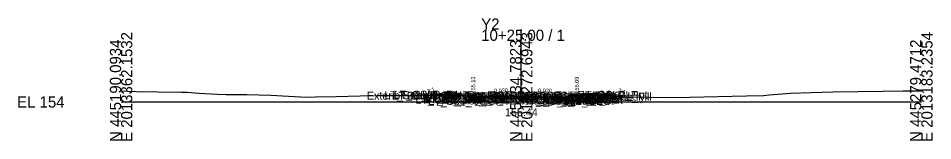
# Model space of a CAD drawing. Extents: x -26 to 203, y -10 to 6017.
# Drawn here: x -25.7 to 202.8, y 490.3 to 520.9 of the extents above; entities that cross this region are included whole.
import ezdxf

# ---------------------------------------------------------------- set-up
doc = ezdxf.new("R2010")
doc.units = 0
for name, color, linetype in [('Default', 7, 'Continuous'), ('Exist CMT Pavement', 7, 'Continuous'), ('Exist Cross Section Cell', 7, 'Continuous'), ('Exist XS Center Line Elevation Label', 7, 'Continuous'), ('Exist XS Ground Line', 7, 'Continuous'), ('Prop CMT Conc Surface', 7, 'Continuous'), ('Prop CMT Concrete Structures', 7, 'Continuous'), ('Prop CMT Pvmt Course 1', 7, 'Continuous'), ('Prop CMT Pvmt Course 1 CG', 7, 'Continuous'), ('Prop CMT Pvmt Course 2', 7, 'Continuous'), ('Prop CMT Pvmt Course 3', 7, 'Continuous'), ('Prop CMT Pvmt Surface', 7, 'Continuous'), ('Prop CMT Pvmt Wedge Surface 1', 7, 'Continuous'), ('Prop CMT Pvmt Wedge Surface 2', 7, 'Continuous'), ('Prop CMT Pvmt Wedge Surface 3', 7, 'Continuous'), ('Prop CMT Slope Grass', 7, 'Continuous'), ('Prop CMT Subgrade Earthwork', 7, 'Continuous'), ('Prop XS Earthwork Shape', 7, 'Continuous'), ('Prop XS Hydro Elevations', 7, 'Continuous'), ('Prop XS SE Text', 7, 'Continuous'), ('Prop XS Side Slope Text', 7, 'Continuous'), ('Scratch_Level_0', 7, 'Continuous')]:
    doc.layers.add(name, color=color, linetype=linetype)

msp = doc.modelspace()

# ---------------------------------------------------------------- linework, layer by layer
at = {"layer": 'Exist CMT Pavement'}
for points in [[(100, 501.44), (99.72, 501.45), (91, 501.36)], [(100, 501.44), (103.09, 501.4), (110.9, 501.16)]]:
    msp.add_lwpolyline(points, dxfattribs=at)
at = {"layer": 'Exist Cross Section Cell'}
for p, q in [((100, 500), (100, 518.08)), ((0, 500), (100, 500)), ((100, 500), (200, 500))]:
    msp.add_line(p, q, dxfattribs=at)
at = {"layer": 'Exist XS Ground Line'}
msp.add_lwpolyline([(0, 502.77), (1.61, 502.73), (3.89, 502.65), (9.07, 502.57), (15.07, 502.46), (16.52, 502.42), (19.43, 502.23), (23.98, 501.98), (26.25, 501.84), (31.43, 501.86), (37.43, 501.69), (41.81, 501.44), (46.34, 501.24), (48.61, 501.28), (53.8, 501.38), (59.79, 501.57), (64.19, 501.63), (70.97, 501.58), (87.75, 501.58), (88.94, 501.44), (89.69, 501.35), (99.72, 501.45), (103.09, 501.4), (111.07, 501.16), (111.56, 501.23), (111.9, 501.66), (124.42, 501.32), (131.99, 501.2), (134.27, 501.15), (142.08, 501.24), (156.34, 501.51), (160.57, 501.64), (162, 501.76), (167.34, 502.2), (172.49, 502.38), (177.94, 502.52), (190.28, 502.7), (195.38, 502.76), (200, 502.79)], dxfattribs=at)
at = {"layer": 'Prop CMT Conc Surface'}
for points in [[(88, 501.13), (88, 501.63), (87.5, 501.63)], [(90, 501.25), (88, 501.13)], [(111.9, 501.21), (113.9, 501.09)], [(113.9, 501.09), (113.9, 501.59), (114.4, 501.59)]]:
    msp.add_lwpolyline(points, dxfattribs=at)
at = {"layer": 'Prop CMT Concrete Structures'}
for points in [[(90, 501.25), (88, 501.13), (88, 501.63), (87.5, 501.63)], [(87.5, 501.63), (87.5, 500.62), (90, 500.67)], [(90, 500.67), (90, 501.25)], [(111.9, 501.21), (113.9, 501.09), (113.9, 501.59), (114.4, 501.59)], [(114.4, 501.59), (114.4, 500.58), (111.9, 500.63)], [(111.9, 500.63), (111.9, 501.21)]]:
    msp.add_lwpolyline(points, dxfattribs=at)
at = {"layer": 'Prop CMT Pvmt Course 1'}
for points in [[(100, 501.45), (90, 501.25)], [(90, 501.25), (90, 501)], [(90, 501), (91, 501.02)], [(91, 501.15), (100, 501.33)], [(91, 501.02), (91, 501.15)], [(100, 501.2), (100, 501.45)], [(100, 501.45), (111.9, 501.21)], [(100, 501.2), (100, 501.45)], [(100, 501.33), (100, 501.2), (100, 501.2)], [(110.9, 501.11), (100, 501.33)], [(100, 501.33), (100, 501.2), (100, 501.2)], [(110.9, 500.98), (110.9, 501.11)], [(111.9, 500.96), (110.9, 500.98)], [(111.9, 501.21), (111.9, 500.96)]]:
    msp.add_lwpolyline(points, dxfattribs=at)
at = {"layer": 'Prop CMT Pvmt Course 1 CG'}
for points in [[(90, 500.67), (87, 500.61), (86.66, 500.27)], [(90, 500.33), (90, 500.67)], [(111.9, 500.63), (114.9, 500.57), (115.24, 500.23)], [(111.9, 500.3), (111.9, 500.63)], [(86.66, 500.27), (90, 500.33)], [(115.24, 500.23), (111.9, 500.3)]]:
    msp.add_lwpolyline(points, dxfattribs=at)
at = {"layer": 'Prop CMT Pvmt Course 2'}
for points in [[(91, 501.02), (90, 501)], [(90, 501), (90, 500.67)], [(90, 500.67), (91, 500.69)], [(91, 500.69), (91, 501.02)], [(110.9, 500.65), (110.9, 500.98)], [(110.9, 500.98), (111.9, 500.96)], [(111.9, 500.63), (110.9, 500.65)], [(111.9, 500.96), (111.9, 500.63)]]:
    msp.add_lwpolyline(points, dxfattribs=at)
at = {"layer": 'Prop CMT Pvmt Course 3'}
for points in [[(91, 500.69), (90, 500.67)], [(90, 500.67), (90, 500.33)], [(91, 500.35), (91, 500.69)], [(110.9, 500.65), (111.9, 500.63)], [(110.9, 500.32), (110.9, 500.65)], [(111.9, 500.63), (111.9, 500.3)], [(90, 500.33), (91, 500.35)], [(111.9, 500.3), (110.9, 500.32)]]:
    msp.add_lwpolyline(points, dxfattribs=at)
at = {"layer": 'Prop CMT Pvmt Surface'}
for points in [[(100, 501.45), (90, 501.25)], [(100, 501.45), (111.9, 501.21)]]:
    msp.add_lwpolyline(points, dxfattribs=at)
at = {"layer": 'Prop CMT Pvmt Wedge Surface 1'}
for points in [[(90, 501), (90, 501.25)], [(91, 501.02), (90, 501)], [(100, 501.33), (91, 501.15)], [(91, 501.15), (91, 501.02)], [(100, 501.33), (110.9, 501.11)], [(110.9, 501.11), (110.9, 500.98)], [(110.9, 500.98), (111.9, 500.96)], [(111.9, 500.96), (111.9, 501.21)]]:
    msp.add_lwpolyline(points, dxfattribs=at)
at = {"layer": 'Prop CMT Pvmt Wedge Surface 2'}
for points in [[(90, 501), (90, 501.25)], [(100, 501.2), (90, 501)], [(100, 501.2), (111.9, 500.96)], [(111.9, 500.96), (111.9, 501.21)]]:
    msp.add_lwpolyline(points, dxfattribs=at)
at = {"layer": 'Prop CMT Pvmt Wedge Surface 3'}
for points in [[(90, 500.67), (90, 501.25)], [(100, 500.87), (90, 500.67)], [(100, 500.87), (111.9, 500.63)], [(111.9, 500.63), (111.9, 501.21)]]:
    msp.add_lwpolyline(points, dxfattribs=at)
at = {"layer": 'Prop CMT Slope Grass'}
for points in [[(87.5, 501.63), (78, 501.82), (77.29, 501.58)], [(114.4, 501.59), (123.9, 501.78), (125.34, 501.3)]]:
    msp.add_lwpolyline(points, dxfattribs=at)
at = {"layer": 'Prop CMT Subgrade Earthwork'}
for points in [[(90, 500.33), (86.66, 500.27), (85.25, 501.68)], [(91, 500.35), (91.01, 501.36)], [(110.9, 500.32), (110.88, 501.16)], [(111.9, 500.3), (115.24, 500.23), (116.65, 501.64)], [(91, 500.35), (90, 500.33)], [(110.9, 500.32), (111.9, 500.3)]]:
    msp.add_lwpolyline(points, dxfattribs=at)
at = {"layer": 'Prop XS Earthwork Shape'}
for points in [[(85.25, 501.68), (78, 501.82), (77.29, 501.58), (85.34, 501.58)], [(85.25, 501.68), (78, 501.82), (77.29, 501.58), (85.34, 501.58)], [(77.29, 501.58), (85.34, 501.58), (85.25, 501.68), (78, 501.82)], [(85.25, 501.68), (78, 501.82), (77.29, 501.58), (85.34, 501.58)], [(85.34, 501.58), (87.5, 501.58), (87.5, 500.62), (90, 500.67), (90, 501.25), (91.01, 501.27), (91, 500.35), (90, 500.33), (86.66, 500.27)], [(85.34, 501.58), (87.5, 501.58), (87.5, 500.62), (90, 500.67), (90, 501.25), (91.01, 501.27), (91, 500.35), (90, 500.33), (86.66, 500.27)], [(85.34, 501.58), (87.5, 501.58), (87.5, 500.62), (90, 500.67), (90, 501.25), (91.01, 501.27), (91, 500.35), (90, 500.33), (86.66, 500.27)], [(85.34, 501.58), (87.5, 501.58), (87.5, 500.62), (90, 500.67), (90, 501.25), (91.01, 501.27), (91, 500.35), (90, 500.33), (86.66, 500.27)], [(87.75, 501.58), (88, 501.56), (88, 501.13), (90, 501.25), (90, 500.67), (87.5, 500.62), (87.5, 501.58)], [(87.75, 501.58), (88, 501.56), (88, 501.13), (90, 501.25), (90, 500.67), (87.5, 500.62), (87.5, 501.58)], [(87.75, 501.58), (88, 501.56), (88, 501.13), (90, 501.25), (90, 500.67), (87.5, 500.62), (87.5, 501.58)], [(87.75, 501.58), (88, 501.56), (88, 501.13), (90, 501.25), (90, 500.67), (87.5, 500.62), (87.5, 501.58)], [(91.01, 501.27), (91.01, 501.36), (91, 501.36), (89.69, 501.35), (88.94, 501.44), (88, 501.56), (88, 501.13), (90, 501.25)], [(91.01, 501.27), (91.01, 501.36), (91, 501.36), (89.69, 501.35), (88.94, 501.44), (88, 501.56), (88, 501.13), (90, 501.25)], [(91.01, 501.27), (91.01, 501.36), (91, 501.36), (89.69, 501.35), (88.94, 501.44), (88, 501.56), (88, 501.13), (90, 501.25)], [(91.01, 501.27), (91.01, 501.36), (91, 501.36), (89.69, 501.35), (88.94, 501.44), (88, 501.56), (88, 501.13), (90, 501.25)], [(91.01, 501.27), (91.01, 501.36), (99.72, 501.45), (100, 501.44)], [(91.01, 501.27), (91.01, 501.36), (99.72, 501.45), (100, 501.44)], [(91.01, 501.27), (91.01, 501.36), (99.72, 501.45), (100, 501.44)], [(91.01, 501.27), (91.01, 501.36), (99.72, 501.45), (100, 501.44)], [(100, 501.44), (103.09, 501.4), (104.66, 501.35)], [(100, 501.44), (104.66, 501.35), (103.09, 501.4)], [(100, 501.44), (103.09, 501.4), (104.66, 501.35)], [(100, 501.44), (103.09, 501.4), (104.66, 501.35)], [(111.51, 501.22), (111.56, 501.23), (111.9, 501.21), (111.9, 500.63), (114.4, 500.58), (114.4, 501.59), (116.55, 501.53), (115.24, 500.23), (111.9, 500.3), (110.9, 500.32), (110.88, 501.16), (110.9, 501.16), (111.07, 501.16)], [(111.56, 501.23), (111.9, 501.21), (111.9, 500.63), (114.4, 500.58), (114.4, 501.59), (116.55, 501.53), (115.24, 500.23), (111.9, 500.3), (110.9, 500.32), (110.88, 501.16), (110.9, 501.16), (111.07, 501.16), (111.51, 501.22)], [(111.56, 501.23), (111.9, 501.21), (111.9, 500.63), (114.4, 500.58), (114.4, 501.59), (116.55, 501.53), (115.24, 500.23), (111.9, 500.3), (110.9, 500.32), (110.88, 501.16), (110.9, 501.16), (111.07, 501.16), (111.51, 501.22)], [(111.51, 501.22), (111.56, 501.23), (111.9, 501.21), (111.9, 500.63), (114.4, 500.58), (114.4, 501.59), (116.55, 501.53), (115.24, 500.23), (111.9, 500.3), (110.9, 500.32), (110.88, 501.16), (110.9, 501.16), (111.07, 501.16)], [(111.56, 501.23), (111.9, 501.21), (113.9, 501.09), (113.9, 501.59), (114.4, 501.59), (111.9, 501.66)], [(111.56, 501.23), (111.9, 501.21), (113.9, 501.09), (113.9, 501.59), (114.4, 501.59), (111.9, 501.66)], [(111.56, 501.23), (111.9, 501.21), (113.9, 501.09), (113.9, 501.59), (114.4, 501.59), (111.9, 501.66)], [(111.56, 501.23), (111.9, 501.21), (113.9, 501.09), (113.9, 501.59), (114.4, 501.59), (111.9, 501.66)], [(111.9, 501.21), (113.9, 501.09), (113.9, 501.59), (114.4, 501.59), (114.4, 500.58), (111.9, 500.63)], [(111.9, 501.21), (113.9, 501.09), (113.9, 501.59), (114.4, 501.59), (114.4, 500.58), (111.9, 500.63)], [(114.4, 501.59), (114.4, 500.58), (111.9, 500.63), (111.9, 501.21), (113.9, 501.09), (113.9, 501.59)], [(111.9, 501.21), (113.9, 501.09), (113.9, 501.59), (114.4, 501.59), (114.4, 500.58), (111.9, 500.63)], [(116.55, 501.53), (124.42, 501.32), (125.34, 501.3), (123.9, 501.78), (116.65, 501.64)], [(116.55, 501.53), (124.42, 501.32), (125.34, 501.3), (123.9, 501.78), (116.65, 501.64)], [(116.55, 501.53), (124.42, 501.32), (125.34, 501.3), (123.9, 501.78), (116.65, 501.64)], [(116.65, 501.64), (123.9, 501.78), (125.34, 501.3), (124.42, 501.32), (116.55, 501.53)]]:
    msp.add_lwpolyline(points, close=True, dxfattribs=at)

# ---------------------------------------------------------------- texts
at = {"layer": 'Default'}
msp.add_text('-', height=0.0001, dxfattribs=at).set_placement((0, 500))
at = {"layer": 'Exist Cross Section Cell'}
for s, p in [('Y2', (90, 518.08)), ('10+25.00 / 1', (90, 515.28)), ('EL 154', (-26, 498.6))]:
    msp.add_text(s, height=2.8, dxfattribs=at).set_placement(p)
for s, p in [('E 2013362.1532', (2.8, 490)), ('E 2013272.6943', (102.8, 490)), ('E 2013183.2354', (202.8, 490)), ('N 445190.0934', (0, 490)), ('N 445234.7823', (100, 490)), ('N 445279.4712', (200, 490))]:
    msp.add_text(s, height=2.8, rotation=90, dxfattribs=at).set_placement(p)
at = {"layer": 'Exist XS Center Line Elevation Label'}
msp.add_text('155.44', height=2, dxfattribs=at).set_placement((95.96, 496.44))
at = {"layer": 'Prop XS Hydro Elevations'}
for s, p in [('155.13', (88.5, 502.13)), ('155.09', (114.4, 502.09))]:
    msp.add_text(s, height=1, rotation=90, dxfattribs=at).set_placement(p)
at = {"layer": 'Prop XS SE Text'}
for rotation, p in [(1.1458, (93.23, 502.32)), (358.8542, (104.22, 502.37))]:
    msp.add_text('0.020', height=1, rotation=rotation, dxfattribs=at).set_placement(p)
at = {"layer": 'Prop XS Side Slope Text'}
for rotation, p in [(18.4332, (76.66, 502.16)), (341.5668, (124.11, 502.5))]:
    msp.add_text('3:1', height=1, rotation=rotation, dxfattribs=at).set_placement(p)
at = {"layer": 'Scratch_Level_0'}
for s, p in [('LT_Sub_Trench_Out_DLT', (65.82, 500.68)), ('LT_CSLP_Pnt', (68.17, 500.82)), ('RT_CSLP_Pnt', (114.03, 500.78)), ('Exterior Boundary', (61.43, 500.58)), ('LT_Slope_Fill', (67.81, 500.58)), ('LT_CG1_Shelf_Out', (73.55, 499.61)), ('LT_CG_Top_Face', (75.26, 500.63)), ('LT_CG_Top_BOC', (75.78, 500.63)), ('LT_CG_Bot_BOC', (75.81, 499.62)), ('LT_PV_Sub_Tie_Out', (75.96, 500.36)), ('LT_CG_Top_Gut', (76.24, 500.13)), ('LT_Sub_OEOP', (76.77, 499.27)), ('LT_PV_OEEOP_EG', (78.54, 500.36)), ('LT_CG_Bot_IE', (79.91, 499.67)), ('LT_Sub_OEOT', (80.08, 499.33)), ('LT_PV2_OEOT', (80.17, 500)), ('LT_PV3_OEOT', (80.17, 499.67)), ('LT_Sub_OEEOP', (80.21, 499.35)), ('LT_PV2_OEEOP', (80.31, 500.02)), ('LT_PV3_OEEOP', (80.31, 499.69)), ('LT_PV1_OEOT', (80.74, 500.25)), ('LT_PV1_OEEOP', (80.87, 500.15)), ('RT_PV_IEEOP_EG', (88.14, 500.44)), ('LT_PV_IEEOP_EG', (88.19, 500.44)), ('RT_PV2_IEEOP', (89.91, 500.2)), ('RT_PV3_IEEOP', (89.91, 499.87)), ('LT_PV2_IEEOP', (89.95, 500.2)), ('LT_PV3_IEEOP', (89.95, 499.87)), ('RT_PV1_IEEOP', (90.47, 500.33)), ('LT_PV1_IEEOP', (90.52, 500.33)), ('PV2_PGL', (93.91, 500.2)), ('PV1_PGL', (94.47, 500.45)), ('RT_PV_Sub_Tie_Out', (95.78, 500.16)), ('RT_Sub_Trench_Out_DLT', (97.17, 500.64)), ('RT_PV_OEEOP_EG', (98.39, 500.16)), ('RT_Sub_OEEOP', (100.06, 499.32)), ('RT_PV2_OEEOP', (100.16, 499.98)), ('RT_PV3_OEEOP', (100.16, 499.65)), ('RT_PV1_OEEOP', (100.72, 500.11)), ('RT_CG_Top_Face', (101.11, 500.59)), ('RT_CG1_Shelf_Out', (101.4, 499.57)), ('RT_CG_Bot_IE', (101.77, 499.63)), ('RT_Sub_OEOT', (101.93, 499.3)), ('RT_PV2_OEOT', (102.03, 499.96)), ('RT_PV3_OEOT', (102.03, 499.63)), ('RT_CG_Top_Gut', (102.09, 500.09)), ('RT_PV1_OEOT', (102.59, 500.21)), ('RT_CG_Top_BOC', (102.64, 500.59)), ('RT_CG_Bot_BOC', (102.67, 499.58)), ('RT_Sub_OEOP', (105.3, 499.23)), ('Exterior Boundary', (109.49, 500.3)), ('RT_Slope_Fill', (115.82, 500.3))]:
    msp.add_text(s, height=2, dxfattribs=at).set_placement(p)

doc.saveas('drawing.dxf')
